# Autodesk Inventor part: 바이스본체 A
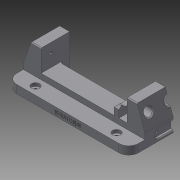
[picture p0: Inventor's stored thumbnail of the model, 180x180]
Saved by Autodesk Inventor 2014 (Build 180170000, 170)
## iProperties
Created: 2017-04
Part Number: 바이스본체 A
Material: 알루미늄 6061
Document SubType Name: Modeling
Designer: mduedu
Density: 2.71 g/cm^3
Appearance: 기본값
Author: mduedu
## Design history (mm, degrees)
sketch "스케치1"
  geometry: L1 (-75, 0)-(75, 0); L2 (-75, 0)-(-75, 17); L3 (-53, 17)-(53, 17); L4 (75, 17)-(75, 0); L5 (-75, 17)-(-65.173, 44); L6 (-65.173, 44)-(-53, 44); L7 (-53, 44)-(-53, 17); L8 (0, 0)-(0, 17); L9 (75, 17)-(65.173, 44); L10 (65.173, 44)-(53, 44); L11 (53, 44)-(53, 17); 1 further point
  constraints: 22 end point, 4 perpendicular, 2 horizontal alignment, 2 midpoint, 2 symmetric about line, 1 coincident, 1 collinear, 1 horizontal, 1 vertical
  dimensions: "d0" = 150 distance of L1.start L1.end; "d1" = 17 distance of L1.start L2.end; "d2" = 27 distance of L3.start L6.end; "d3" = 22 distance of L3.start L2.end; "d4" = 70 deg angle of L3 L5; "d54" = 20 deg angle of L9 L4
extrude "돌출1" new body sketch "스케치1" stored distance "d5" = 70; taper "d6" = 0 deg
sketch "스케치2"
  geometry: L1 (0, 70)-(106, 70) reference; L2 (106, 70)-(106, 0) reference; L3 (106, 0)-(0, 0) reference; L4 (0, 47)-(106, 47); L5 (106, 47)-(106, 23); L6 (106, 23)-(0, 23); L7 (0, 23)-(0, 47); L8 (0, 70)-(0, 0) reference; 2 further points
  constraints: 8 end point, 2 parallel, 2 point on line, 1 horizontal, 1 horizontal alignment, 1 midpoint, 1 perpendicular
  dimensions: "d7" = 24 distance between parallel lines of L6 L4
extrude "돌출2" cut sketch "스케치2" stored distance "d9" = 70; taper "d10" = 0 deg
sketch "스케치3"
  geometry: L1 (22, -23)-(128, -23) reference; L2 (128, -47)-(22, -47) reference; L3 (22, -18)-(128, -18); L4 (128, -52)-(22, -52); L5 (22, -18)-(22, -52); L6 (128, -18)-(128, -52); 1 further point
  constraints: 8 end point, 3 parallel, 2 point on line, 1 perpendicular
  dimensions: "d11" = 5 distance between parallel lines of L3 L1; "d12" = 5 distance between parallel lines of L4 L2
extrude "돌출3" cut sketch "스케치3" distance "d13" = 12; taper "d14" = 0 deg
fillet "모깎기1" dims "d15" = 3, "d16" = 3
sketch "스케치4"
  geometry: L1 (103, 23)-(3, 23) reference; L2 (0, 26)-(0, 0) reference; L3 (106, 0)-(0, 0) reference; L4 (106, 26)-(106, 0) reference; L5 (96, 0)-(90, 0); L6 (90, 0)-(90, 19.5); L7 (96, 19.5)-(96, 0); L8 (90, 19.5)-(96, 19.5); A1 r 3 centre (3, 26) between (0, 26) and (3, 23) reference; A2 r 3 centre (103, 26) between (103, 23) and (106, 26) reference; 1 further point
  constraints: 8 end point, 2 perpendicular, 1 horizontal, 1 parallel, 1 point on line
  dimensions: "d17" = 10 distance between parallel lines of L7 L4; "d18" = 6 distance between parallel lines of L7 L6; "d27" = 3.5 distance between parallel lines of L8 L1
extrude "돌출4" join sketch "스케치4" distance "d19" = 12; taper "d20" = 0 deg
chamfer "모따기1" distance "d21" = 3; stored, may be unused: second distance "d22" = 2, angle "d23" = 45 deg
chamfer "모따기2" distance "d24" = 3; stored, may be unused: second distance "d25" = 2, angle "d26" = 45 deg
sketch "스케치5"
  geometry: L1 (-15.5, 35.8)-(-15.5, -25.8) reference; L2 (19.5, 0)-(0, 0) reference; C1 r 6.5 at (9.5, 15); 1 further point
  constraints: 1 centre point
  dimensions: "d28" = 13 diameter of C1; "d30" = 15 distance from line of C1.centre L2; "d31" = 25 distance from line of C1.centre L1
extrude "돌출5" cut sketch "스케치5" stored distance "d32" = 12; taper "d33" = 0 deg
sketch "스케치6"
  geometry: C1 r 5 at (-10, 15); C2 r 5 at (-60, 15); A1 r 6.5 centre (-10, 15) between (-15.766, 12) and (-4.234, 12) reference; A2 r 6.5 centre (-60, 15) between (-65.766, 12) and (-54.234, 12) reference; 1 further point
  constraints: 2 centre point, 2 coincident
  dimensions: "d34" = 10 diameter of C1; "d35" = 10 diameter of C2 (= d34)
extrude "돌출6" cut sketch "스케치6" stored distance "d36" = 12; taper "d37" = 0 deg
chamfer "모따기3" distance "d38" = 1; stored, may be unused: second distance "d39" = 2, angle "d40" = 45 deg
chamfer "모따기4" distance "d41" = 1; stored, may be unused: second distance "d42" = 2, angle "d43" = 45 deg
sketch "스케치7"
  geometry: L1 (-35, 35.8)-(-35, -25.8) reference; L2 (-70, 0)-(0, 0) reference; C1 r 5 at (-35, 15); 1 further point
  constraints: 1 centre point, 1 point on line
  dimensions: "d44" = 10 diameter of C1; "d45" = 15 distance from line of C1.centre L2
extrude "돌출7" cut sketch "스케치7" stored distance "d46" = 12; taper "d47" = 0 deg
chamfer "모따기5" distance "d48" = 1; stored, may be unused: second distance "d49" = 2, angle "d50" = 45 deg
node "작업축1"
sketch "스케치8"
  geometry: L1 (-105, 32)-(105, 32) reference; L2 (58, 32)-(64, 32); L3 (64, 32)-(64, 40); L4 (64, 40)-(58, 40); L5 (58, 40)-(58, 32); L6 (53, 38)-(53, 26) reference; 1 further point
  constraints: 8 end point, 2 parallel, 1 horizontal, 1 perpendicular, 1 point on line
  dimensions: "d51" = 5 distance from line of L6 L2.start; "d52" = 6 distance of L3.end L4.end; "d53" = 16 diameter of L4 L1
revolve "회전1" sketch "스케치8" stored, may be unused: angle "d55" = 90 deg
fillet "모깎기2"
chamfer "모따기6" distance "d56" = 1; stored, may be unused: second distance "d57" = 2, angle "d58" = 45 deg
sketch "스케치9"
  geometry: L1 (17.5, 3)-(52.5, 3); L2 (52.5, 13)-(17.5, 13); L3 (70, 0)-(0, 0) reference; L4 (17.5, 8)-(52.5, 8); A1 r 5 centre (17.5, 8) between (17.5, 13) and (17.5, 3); A2 r 5 centre (52.5, 8) between (52.5, 3) and (52.5, 13); 3 further points
  constraints: 6 end point, 4 point on circle, 3 tangent, 2 centre point, 2 midpoint, 2 parallel, 1 horizontal, 1 vertical alignment
  dimensions: "d59" = 35 distance of L4.start L4.end; "d61" = 5 radius of A2; "d62" = 8 distance between parallel lines of L3 L4
extrude "돌출8" cut sketch "스케치9" distance "d63" = 3; taper "d64" = 0 deg
chamfer "모따기7" distance "d65" = 1; stored, may be unused: second distance "d66" = 2, angle "d67" = 45 deg
chamfer "모따기8" distance "d68" = 1; stored, may be unused: second distance "d69" = 2, angle "d70" = 45 deg
feature "분할1"
sketch "스케치10"
  geometry: L1 (35, 27)-(0, 27) reference; L2 (0, 0)-(0, 27) reference; 1 further point
  dimensions: "d85" = 11.5 distance from line of point (12, 15.5) L1; "d86" = 12 distance from line of point (12, 15.5) L2
hole "구멍1" sketch "스케치10" at (12, 15.5) diameter "d71" = 3.242; stored, may be unused: countersink angle "d75" = 90 deg, drill point angle "d77" = 120 deg; dims "d72" = 6, "d73" = 4, "d74" = 2, "d76" = 8
sketch "스케치11"
  geometry: A1 r 5 centre (17.5, 8) between (17.5, 13) and (17.5, 3) reference; 1 further point
  constraints: 1 coincident
hole "구멍3" sketch "스케치11" at (17.5, 8) diameter "d78" = 2.459; stored, may be unused: countersink angle "d82" = 90 deg, drill point angle "d84" = 120 deg; dims "d79" = 4.5, "d80" = 4, "d81" = 2, "d83" = 6
sketch "스케치13"
  geometry: L1 (75, 0)-(75, 35) reference; L2 (-75, 0)-(-75, 35) reference; L3 (-75, 35)-(75, 35); L4 (75, 35)-(75, 55); L5 (75, 55)-(-75, 55); L6 (-75, 55)-(-75, 35); 1 further point
  constraints: 8 end point, 2 parallel, 1 horizontal, 1 perpendicular, 1 point on line
  dimensions: "d90" = 20 distance between parallel lines of L5 L3; "d94" = 150 distance of L4.end L5.end (derived)
extrude "돌출9" join sketch "스케치13" distance "d92" = 10; taper "d93" = 0 deg
sketch "스케치14"
  geometry: L1 (-75, -35)-(-75, -55) reference; L2 (75, -55)-(75, -35) reference; L3 (-75, -45)-(75, -45); 3 further points
  constraints: 2 end point, 2 midpoint, 2 point on line
  dimensions: "d95" = 50 horizontal distance of point (-50, -45) point (0, 0); "d96" = 100 distance of point (50, -45) point (-50, -45)
fillet "모깎기3" dims "d97" = 12
chamfer "모따기9" distance "d98" = 1; stored, may be unused: second distance "d99" = 2, angle "d100" = 45 deg
hole "구멍4" sketch "스케치14" diameter "d101" = 4.134; stored, may be unused: countersink angle "d105" = 90 deg, drill point angle "d107" = 118 deg; dims "d102" = 6, "d103" = 10, "d104" = 4, "d106" = 8
sketch "스케치15"
  geometry: L1 (0, 0)-(126, 0) reference; 3 further points
  constraints: 1 midpoint, 1 vertical alignment, 1 other
  dimensions: "d109" = 5 distance from line of point (63, 5) L1
feature "엠보싱2" sketch "스케치15" dims "d0" = 150, "d1" = 17, "d2" = 27, "d3" = 22, "d4" = 70 deg, "d54" = 20 deg, "d110" = 0.5, "d111" = 0
node "솔리드1"
mirror "대칭1"
mirror "대칭2"
mirror "대칭3"
mirror "대칭4"
node "투영된 루프1"
